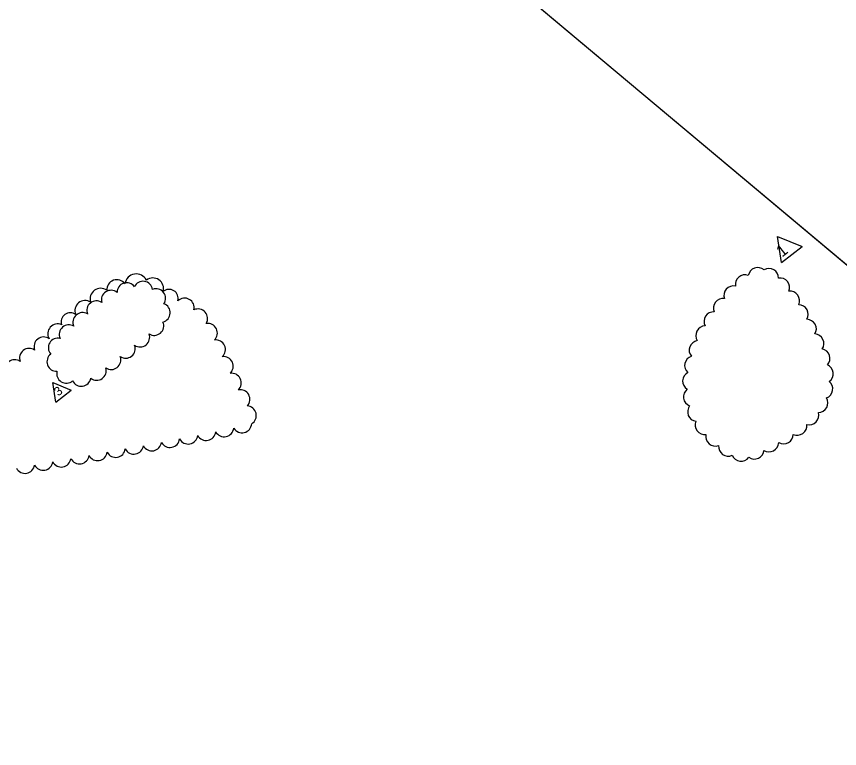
# Model space of a CAD drawing. Extents: x 2174973 to 2176977, y 76106 to 78055.
# Drawn here: x 2176114.2 to 2176531.4, y 77309.7 to 77680.6 of the extents above; entities that cross this region are included whole.
import ezdxf

# ---------------------------------------------------------------- set-up
doc = ezdxf.new("R2010")
doc.units = 0
for name, color, linetype in [('CTL Primary Horizontal and Vertical CELL', 7, 'Continuous'), ('Exist Structure Minor Pipes RCP 18 Inch', 7, 'Continuous'), ('Exist Utilities Other Traffic Signal Box CELL', 7, 'Continuous')]:
    doc.layers.add(name, color=color, linetype=linetype)

msp = doc.modelspace()

# ---------------------------------------------------------------- linework, layer by layer
at = {"layer": 'CTL Primary Horizontal and Vertical CELL'}
msp.add_lwpolyline([(2175306.56, 76817.11), (2175665.08, 76359.73), (2175813.77, 76476.34), (2175916.67, 76345.14), (2176696.59, 76956.56), (2176763.63, 77051.2), (2176889.59, 77229), (2176824.75, 77311.73), (2176559.15, 77534.36), (2176539.41, 77550.91), (2176367.65, 77694.89), (2176358.97, 77688.08), (2176301.94, 77760.83), (2176250.28, 77720.34), (2176235.78, 77738.83), (2176166.38, 77827.37), (2176143.21, 77856.93), (2175957.17, 77711.1), (2175525.72, 77372.91), (2175451.32, 77314.59), (2175120.11, 77054.97)], close=True, dxfattribs=at)
at = {"layer": 'Exist Structure Minor Pipes RCP 18 Inch'}
for p, q in [((2176499.99, 77569.21), (2176512.44, 77564.06)), ((2176502.02, 77555.89), (2176499.99, 77569.21)), ((2176502.02, 77555.89), (2176512.44, 77564.06)), ((2176132.6, 77495.2), (2176141.94, 77491.34)), ((2176134.12, 77485.21), (2176132.6, 77495.2)), ((2176134.12, 77485.21), (2176141.94, 77491.34))]:
    msp.add_line(p, q, dxfattribs=at)
for centre, radius, start, end in [((2176489.93, 77548.5), 4.89, 49.2993, 169.2993), ((2176495.62, 77548), 4.89, 0.7738, 120.7738), ((2176165.16, 77542.09), 5.14, 37.5112, 182.5112), ((2176174.96, 77544.39), 5.79, 26.7497, 171.7497), ((2176178.43, 77541.55), 4.87, 9.3261, 154.3261), ((2176183.43, 77542.77), 5.37, 342.9415, 127.9415), ((2176483.45, 77544.81), 4.89, 69.9716, 189.9716), ((2176501.19, 77543.23), 4.89, 338.091, 98.091), ((2176156.9, 77537.58), 5.31, 53.8966, 198.8966), ((2176170.09, 77540.82), 4.87, 35.6771, 180.6771), ((2176184.97, 77537.79), 4.86, 325.8961, 110.8961), ((2176191.6, 77537.7), 4.63, 346.0454, 131.0454), ((2176477.64, 77539.18), 4.89, 78.207, 198.207), ((2176162.14, 77537), 4.87, 50.5603, 195.5603), ((2176199.43, 77533.01), 4.89, 347.9555, 132.9555), ((2176506.24, 77536.55), 4.88, 336.0323, 96.0323), ((2176149.06, 77531.52), 5.18, 57.0386, 202.0386), ((2176154.76, 77531.64), 4.87, 56.4755, 201.4755), ((2176187.29, 77530.51), 4.86, 284.4281, 69.4281), ((2176472.37, 77532.81), 4.89, 82.6098, 202.6098), ((2176510.61, 77529.68), 4.89, 328.9767, 88.9767), ((2176141.53, 77525.86), 4.61, 53.6422, 198.6422), ((2176147.74, 77525.69), 4.87, 59.0712, 204.0712), ((2176206.24, 77527.53), 4.89, 329.5471, 114.5471), ((2176467.59, 77526.05), 4.89, 86.8692, 206.8692), ((2176184.02, 77523.9), 4.87, 238.0175, 23.0175), ((2176514.72, 77522.27), 4.89, 328.9767, 88.9767), ((2176135.09, 77519.87), 4.97, 65.3987, 210.3987), ((2176140.8, 77519.52), 4.87, 59.2125, 204.2125), ((2176211.2, 77520.22), 4.89, 313.7276, 98.7276), ((2176463.42, 77518.96), 4.89, 92.2351, 212.2351), ((2176128.04, 77513.32), 4.89, 55.591, 200.591), ((2176135.26, 77512.79), 4.86, 76.8881, 221.8881), ((2176176.89, 77518.05), 4.87, 235.6944, 20.6944), ((2176518.56, 77514.88), 4.89, 326.0057, 86.0057), ((2176169.59, 77512.32), 4.87, 235.591, 20.591), ((2176215.25, 77511.83), 4.89, 312.8383, 97.8383), ((2176460.06, 77511.52), 4.89, 99.0621, 219.0621), ((2176120.69, 77507.56), 4.89, 55.591, 200.591), ((2176134.59, 77505.68), 4.87, 127.3824, 272.3824), ((2176521.59, 77507.36), 4.89, 317.8879, 77.8879), ((2176113.35, 77501.81), 4.89, 55.591, 200.591), ((2176162.29, 77506.6), 4.87, 235.591, 20.591), ((2176219.22, 77503.4), 4.89, 312.5499, 97.5499), ((2176457.75, 77503.79), 4.89, 107.6941, 227.6941), ((2176139.52, 77499.65), 4.87, 166.1297, 311.1297), ((2176154.89, 77501.15), 4.87, 232.1468, 17.1468), ((2176523.25, 77499.61), 4.89, 306.2999, 66.2999), ((2176147.1, 77498.09), 4.87, 205.7048, 350.7048), ((2176223.28, 77494.96), 4.89, 313.7996, 98.7996), ((2176456.74, 77495.85), 4.89, 117.8174, 237.8174), ((2176523.04, 77491.9), 4.89, 290.522, 50.522), ((2176227.67, 77486.63), 4.89, 316.8388, 101.8388), ((2176457.18, 77487.9), 4.89, 128.5904, 248.5904), ((2176520.58, 77484.78), 4.89, 271.3427, 31.3427), ((2176230.92, 77478.41), 4.89, 301.2766, 86.2766), ((2176459.26, 77480.34), 4.89, 142.0685, 262.0685), ((2176515.99, 77478.56), 4.89, 255.915, 15.915), ((2176463.08, 77473.6), 4.89, 157.0487, 277.0487), ((2176219.51, 77472.53), 4.89, 209.4135, 354.4135), ((2176228.58, 77474.57), 4.89, 211.0003, 356.0003), ((2176509.94, 77473.34), 4.89, 245.6374, 5.6374), ((2176201.24, 77468.87), 4.89, 208.3881, 353.3881), ((2176210.39, 77470.66), 4.89, 208.7665, 353.7665), ((2176468.48, 77467.81), 4.89, 168.9296, 288.9296), ((2176503.04, 77468.93), 4.89, 239.4708, 359.4708), ((2176173.73, 77463.74), 4.89, 207.7978, 352.7978), ((2176182.9, 77465.42), 4.89, 207.9437, 352.9437), ((2176192.07, 77467.12), 4.89, 208.132, 353.132), ((2176474.93, 77462.73), 4.89, 174.7255, 294.7255), ((2176495.67, 77464.91), 4.89, 237.7446, 357.7446), ((2176155.36, 77460.44), 4.89, 207.5833, 352.5833), ((2176164.55, 77462.08), 4.89, 207.6804, 352.6804), ((2176488.2, 77461.23), 4.89, 234.6969, 354.6969), ((2176127.79, 77455.59), 4.89, 207.3763, 352.3763), ((2176136.98, 77457.2), 4.89, 207.4307, 352.4307), ((2176146.17, 77458.81), 4.89, 207.5012, 352.5012), ((2176481.48, 77460.19), 4.89, 202.8468, 322.8468), ((2176118.59, 77453.99), 4.89, 207.386, 352.386)]:
    msp.add_arc(centre, radius, start, end, dxfattribs=at)
at = {"layer": 'Exist Utilities Other Traffic Signal Box CELL'}
msp.add_line((2176824.75, 77311.73), (2176367.65, 77694.89), dxfattribs=at)

# ---------------------------------------------------------------- texts
at = {"layer": 'Exist Structure Minor Pipes RCP 18 Inch'}
for s, height, p in [(' 1', 6, (2176500.46, 77557.01)), ('3', 4.5, (2176135.46, 77488.02))]:
    msp.add_text(s, height=height, rotation=38.091, dxfattribs=at).set_placement(p)

doc.saveas('drawing.dxf')
